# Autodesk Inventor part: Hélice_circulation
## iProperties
Shininess: 64.0
Length Units: 11269
Angle Units: 11279
Time Units: 11290
Mass Units: 11283
Length Display Precision: 3
Angle Display Precision: 2
Compacted: True
Part Number: Hélice_circulation
Document SubType Name: Modeling
Created: 2008-02
Material: Acier inoxydable, austénitique
Designer: Pascal
Density: 8.03 g/cm^3
Density: 0.0
Volumn: 0.0
Area: 0.0
PropertySet Name: Model Information
Control State: 0
Master: False
Checked Out: False
DESIGNATION: Hélice de circulation
Author: Pascal
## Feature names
1. Hélicoïde1
